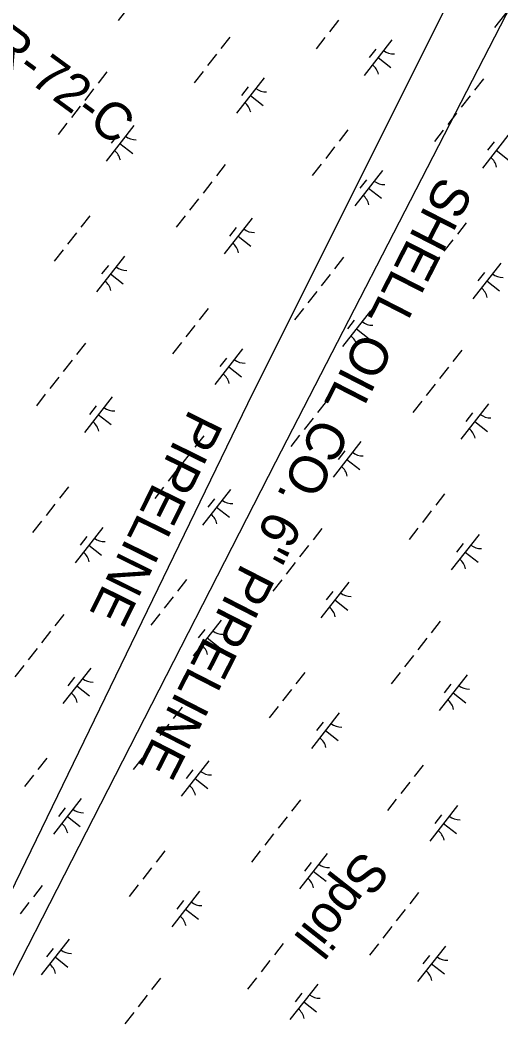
# Model space of a CAD drawing. Extents: x 3896831 to 3918110, y 171006 to 193349.
# Drawn here: x 3907043 to 3907575, y 175242 to 176349 of the extents above; entities that cross this region are included whole.
import ezdxf

# ---------------------------------------------------------------- set-up
doc = ezdxf.new("R2010")
doc.units = 0
for name, color, linetype in [('V-CHAN-SPOL', 7, 'Continuous'), ('V-RIVR-RANG-IDEN', 7, 'Continuous'), ('V-UTIL-IDEN', 7, 'Continuous'), ('V-UTIL-LINE', 7, 'Continuous'), ('V-WETL-SWMP', 7, 'Continuous')]:
    doc.layers.add(name, color=color, linetype=linetype)

msp = doc.modelspace()

# ---------------------------------------------------------------- linework, layer by layer
at = {"layer": 'V-UTIL-LINE'}
for points in [[(3905549.4, 173652.6), (3906763.3, 174938.4), (3906949.5, 175133), (3906970.6, 175166.8), (3907325.9, 175860.5), (3907748.9, 176681), (3908142.2, 177273.2), (3908679.4, 178098), (3908869.7, 178381.4), (3908937.4, 178537.8), (3909170, 179117.3), (3909533.8, 179633.3), (3910092.1, 180424.3), (3910333.2, 180766.9), (3910760.4, 181291.4), (3910921.1, 181524), (3911225.6, 181951.2), (3911822, 182788.6), (3911961.6, 182987.4), (3912147.7, 183114.3), (3912722.9, 183841.8), (3913090.9, 184307.1), (3913848, 185258.8), (3914364, 185910.1)], [(3913133.2, 183520.4), (3913116.3, 183516.1), (3912989.4, 183516.1), (3912744.1, 183393.5), (3911902.4, 182441.8), (3910866.1, 181249.1), (3910603.9, 180953), (3910214.7, 180504.6), (3910138.6, 180390.4), (3909757.9, 179819.4), (3909457.6, 179366.9), (3909009.3, 178685.9), (3908785.1, 178351.7), (3908150.7, 177400.1), (3907770, 176816.4), (3907693.9, 176706.4), (3907647.3, 176630.3), (3907300.5, 175936.6), (3907025.6, 175369.8), (3906945.2, 175204.9), (3906416.5, 174650.8), (3905507.1, 173682.2)]]:
    msp.add_lwpolyline(points, dxfattribs=at)
at = {"layer": 'V-WETL-SWMP'}
for p, q in [((3907182.1, 176388.1), (3907151.2, 176348.7)), ((3907598.7, 176380.4), (3907567.9, 176341)), ((3907395.1, 176349), (3907385.2, 176336.4)), ((3907274.8, 176330.3), (3907264.9, 176317.7)), ((3907380.2, 176330.1), (3907370.4, 176317.5)), ((3907454.4, 176327.4), (3907423.5, 176288)), ((3907436.6, 176317.2), (3907429.2, 176307.8)), ((3907260, 176311.4), (3907250.1, 176298.8)), ((3907439, 176307.7), (3907453.1, 176296.6)), ((3907245.2, 176292.5), (3907235.3, 176279.9)), ((3907138.9, 176291.9), (3907129.1, 176279.3)), ((3907313, 176285.5), (3907282.1, 176246.1)), ((3907555.6, 176284.2), (3907545.7, 176271.6)), ((3907124.1, 176273), (3907114.3, 176260.4)), ((3907295.2, 176275.3), (3907287.8, 176265.8)), ((3907297.6, 176265.8), (3907311.7, 176254.7)), ((3907540.8, 176265.3), (3907530.9, 176252.7)), ((3907109.3, 176254.1), (3907099.5, 176241.5)), ((3907526, 176246.4), (3907516.1, 176233.8)), ((3907094.5, 176235.2), (3907084.7, 176222.6)), ((3907168.7, 176232.5), (3907137.8, 176193.1)), ((3907405.7, 176227.7), (3907395.8, 176215.1)), ((3907511.2, 176227.5), (3907501.3, 176214.9)), ((3907150.9, 176222.3), (3907143.5, 176212.9)), ((3907585.3, 176224.8), (3907554.5, 176185.4)), ((3907567.5, 176214.6), (3907560.1, 176205.2)), ((3907153.2, 176212.8), (3907167.4, 176201.7)), ((3907390.9, 176208.8), (3907381, 176196.2)), ((3907569.9, 176205.1), (3907584, 176194)), ((3907269.9, 176189.3), (3907260, 176176.7)), ((3907376.1, 176189.9), (3907366.2, 176177.3)), ((3907443.9, 176182.8), (3907413.1, 176143.5)), ((3907255.1, 176170.4), (3907245.2, 176157.8)), ((3907426.1, 176172.6), (3907418.7, 176163.2)), ((3907428.5, 176163.2), (3907442.7, 176152.1)), ((3907240.2, 176151.5), (3907230.4, 176138.9)), ((3907120, 176132.7), (3907110.1, 176120.2)), ((3907225.4, 176132.6), (3907215.6, 176120)), ((3907299.6, 176129.9), (3907268.7, 176090.5)), ((3907281.8, 176119.7), (3907274.4, 176110.2)), ((3907536.6, 176125), (3907526.8, 176112.5)), ((3907105.2, 176113.9), (3907095.3, 176101.3)), ((3907284.2, 176110.2), (3907298.3, 176099.1)), ((3907521.8, 176106.2), (3907511.9, 176093.6)), ((3907090.4, 176095), (3907080.5, 176082.4)), ((3907158.2, 176087.9), (3907127.3, 176048.6)), ((3907400.8, 176086.7), (3907390.9, 176074.1)), ((3907507, 176087.3), (3907497.1, 176074.7)), ((3907140.4, 176077.7), (3907133, 176068.3)), ((3907574.8, 176080.2), (3907544, 176040.9)), ((3907142.8, 176068.3), (3907156.9, 176057.2)), ((3907386, 176067.8), (3907376.1, 176055.2)), ((3907557, 176070), (3907549.6, 176060.6)), ((3907559.4, 176060.6), (3907573.6, 176049.5)), ((3907371.2, 176048.9), (3907361.3, 176036.3)), ((3907250.9, 176030.1), (3907241, 176017.5)), ((3907356.4, 176030), (3907346.5, 176017.4)), ((3907430.5, 176027.3), (3907399.7, 175987.9)), ((3907412.7, 176017.1), (3907405.3, 176007.6)), ((3907236.1, 176011.2), (3907226.2, 175998.7)), ((3907415.1, 176007.6), (3907429.2, 175996.5)), ((3907115.1, 175991.8), (3907105.2, 175979.2)), ((3907221.3, 175992.4), (3907211.4, 175979.8)), ((3907289.1, 175985.3), (3907258.3, 175946)), ((3907531.7, 175984.1), (3907521.8, 175971.5)), ((3907100.2, 175972.9), (3907090.4, 175960.3)), ((3907271.3, 175975.1), (3907263.9, 175965.7)), ((3907273.7, 175965.6), (3907287.9, 175954.5)), ((3907516.9, 175965.2), (3907507, 175952.6)), ((3907085.4, 175954), (3907075.6, 175941.4)), ((3907502.1, 175946.3), (3907492.2, 175933.7)), ((3907070.6, 175935.1), (3907060.8, 175922.5)), ((3907144.8, 175932.4), (3907113.9, 175893)), ((3907381.8, 175927.5), (3907371.9, 175914.9)), ((3907487.3, 175927.4), (3907477.4, 175914.8)), ((3907127, 175922.2), (3907119.6, 175912.7)), ((3907561.4, 175924.7), (3907530.6, 175885.3)), ((3907129.3, 175912.7), (3907143.5, 175901.6)), ((3907367, 175908.6), (3907357.1, 175896)), ((3907543.6, 175914.5), (3907536.2, 175905)), ((3907546, 175905), (3907560.2, 175893.9)), ((3907246, 175889.2), (3907236.1, 175876.6)), ((3907352.2, 175889.8), (3907342.3, 175877.2)), ((3907420, 175882.7), (3907389.2, 175843.4)), ((3907402.2, 175872.5), (3907394.8, 175863.1)), ((3907231.2, 175870.3), (3907221.3, 175857.7)), ((3907404.6, 175863), (3907418.8, 175851.9)), ((3907216.4, 175851.4), (3907206.5, 175838.8)), ((3907096.1, 175832.6), (3907086.2, 175820)), ((3907201.6, 175832.5), (3907191.7, 175819.9)), ((3907275.7, 175829.8), (3907244.8, 175790.4)), ((3907257.9, 175819.6), (3907250.5, 175810.1)), ((3907512.7, 175824.9), (3907502.9, 175812.3)), ((3907081.3, 175813.7), (3907071.4, 175801.1)), ((3907260.3, 175810.1), (3907274.4, 175799)), ((3907497.9, 175806), (3907488.1, 175793.4)), ((3907066.5, 175794.8), (3907056.6, 175782.3)), ((3907134.3, 175787.8), (3907103.5, 175748.5)), ((3907376.9, 175786.6), (3907367, 175774)), ((3907483.1, 175787.1), (3907473.3, 175774.6)), ((3907116.5, 175777.6), (3907109.1, 175768.2)), ((3907550.9, 175780.1), (3907520.1, 175740.8)), ((3907118.9, 175768.1), (3907133, 175757)), ((3907362.1, 175767.7), (3907352.2, 175755.1)), ((3907533.1, 175769.9), (3907525.7, 175760.5)), ((3907535.5, 175760.4), (3907549.7, 175749.3)), ((3907347.3, 175748.8), (3907337.4, 175736.2)), ((3907227, 175730), (3907217.1, 175717.4)), ((3907332.5, 175729.9), (3907322.6, 175717.3)), ((3907406.6, 175727.1), (3907375.8, 175687.8)), ((3907388.8, 175717), (3907381.4, 175707.5)), ((3907212.2, 175711.1), (3907202.3, 175698.5)), ((3907391.2, 175707.5), (3907405.4, 175696.4)), ((3907091.2, 175691.6), (3907081.3, 175679)), ((3907197.4, 175692.2), (3907187.5, 175679.6)), ((3907265.2, 175685.2), (3907234.4, 175645.8)), ((3907507.8, 175683.9), (3907497.9, 175671.3)), ((3907076.4, 175672.8), (3907066.5, 175660.2)), ((3907247.4, 175675), (3907240, 175665.6)), ((3907249.8, 175665.5), (3907264, 175654.4)), ((3907493, 175665.1), (3907483.1, 175652.5)), ((3907061.6, 175653.9), (3907051.7, 175641.3)), ((3907478.2, 175646.2), (3907468.3, 175633.6)), ((3907046.7, 175635), (3907036.9, 175622.4)), ((3907120.9, 175632.2), (3907090, 175592.9)), ((3907103.1, 175622), (3907095.7, 175612.6)), ((3907357.9, 175627.4), (3907348.1, 175614.8)), ((3907463.4, 175627.3), (3907453.5, 175614.7)), ((3907537.5, 175624.5), (3907506.7, 175585.2)), ((3907105.5, 175612.6), (3907119.6, 175601.5)), ((3907343.1, 175608.5), (3907333.3, 175595.9)), ((3907519.7, 175614.3), (3907512.3, 175604.9)), ((3907522.1, 175604.9), (3907536.3, 175593.8)), ((3907222.1, 175589), (3907212.2, 175576.4)), ((3907328.3, 175589.6), (3907318.4, 175577)), ((3907396.1, 175582.6), (3907365.3, 175543.2)), ((3907378.3, 175572.4), (3907370.9, 175563)), ((3907207.3, 175570.1), (3907197.4, 175557.6)), ((3907380.7, 175562.9), (3907394.9, 175551.8)), ((3907192.5, 175551.3), (3907182.6, 175538.7)), ((3907072.2, 175532.5), (3907062.3, 175519.9)), ((3907177.7, 175532.4), (3907167.8, 175519.8)), ((3907251.8, 175529.6), (3907221, 175490.3)), ((3907234, 175519.4), (3907226.6, 175510)), ((3907488.8, 175524.8), (3907479, 175512.2)), ((3907057.4, 175513.6), (3907047.5, 175501)), ((3907236.4, 175510), (3907250.5, 175498.9)), ((3907474, 175505.9), (3907464.2, 175493.3)), ((3907110.4, 175487.7), (3907079.6, 175448.3)), ((3907353, 175486.4), (3907343.1, 175473.8)), ((3907459.2, 175487), (3907449.4, 175474.4)), ((3907092.6, 175477.5), (3907085.2, 175468)), ((3907527.1, 175480), (3907496.2, 175440.6)), ((3907095, 175468), (3907109.2, 175456.9)), ((3907338.2, 175467.5), (3907328.3, 175454.9)), ((3907509.3, 175469.8), (3907501.9, 175460.3)), ((3907511.6, 175460.3), (3907525.8, 175449.2)), ((3907323.4, 175448.6), (3907313.5, 175436.1)), ((3907203.1, 175429.9), (3907193.3, 175417.3)), ((3907308.6, 175429.8), (3907298.7, 175417.2)), ((3907382.7, 175427), (3907351.9, 175387.7)), ((3907188.3, 175411), (3907178.4, 175398.4)), ((3907364.9, 175416.8), (3907357.5, 175407.4)), ((3907367.3, 175407.3), (3907381.5, 175396.2)), ((3907067.3, 175391.5), (3907057.4, 175378.9)), ((3907173.5, 175392.1), (3907163.6, 175379.5)), ((3907241.3, 175385.1), (3907210.5, 175345.7)), ((3907483.9, 175383.8), (3907474, 175371.2)), ((3907223.5, 175374.9), (3907216.1, 175365.4)), ((3907052.5, 175372.6), (3907042.6, 175360)), ((3907225.9, 175365.4), (3907240.1, 175354.3)), ((3907469.1, 175364.9), (3907459.2, 175352.3)), ((3907454.3, 175346), (3907444.4, 175333.4)), ((3907097, 175332.1), (3907066.2, 175292.8)), ((3907079.2, 175321.9), (3907071.8, 175312.5)), ((3907334, 175327.3), (3907324.2, 175314.7)), ((3907439.5, 175327.1), (3907429.6, 175314.6)), ((3907513.6, 175324.4), (3907482.8, 175285.1)), ((3907081.6, 175312.4), (3907095.7, 175301.3)), ((3907319.2, 175308.4), (3907309.4, 175295.8)), ((3907495.8, 175314.2), (3907488.4, 175304.8)), ((3907498.2, 175304.7), (3907512.4, 175293.6)), ((3907198.2, 175288.9), (3907188.3, 175276.3)), ((3907304.4, 175289.5), (3907294.6, 175276.9)), ((3907372.2, 175282.5), (3907341.4, 175243.1)), ((3907183.4, 175270), (3907173.5, 175257.4)), ((3907354.5, 175272.3), (3907347.1, 175262.8)), ((3907356.8, 175262.8), (3907371, 175251.7)), ((3907168.6, 175251.1), (3907158.7, 175238.5))]:
    msp.add_line(p, q, dxfattribs=at)
for centre, start, end in [((3907456.2, 176329.3), 231.1403, 272.6839), ((3907422.1, 176285.8), 11.1403, 52.6839), ((3907314.8, 176287.4), 231.1403, 272.6839), ((3907280.7, 176243.9), 11.1403, 52.6839), ((3907170.5, 176234.4), 231.1403, 272.6839), ((3907136.4, 176190.9), 11.1403, 52.6839), ((3907553, 176183.2), 11.1403, 52.6839), ((3907445.7, 176184.8), 231.1403, 272.6839), ((3907411.6, 176141.3), 11.1403, 52.6839), ((3907301.4, 176131.8), 231.1403, 272.6839), ((3907267.3, 176088.3), 11.1403, 52.6839), ((3907160, 176089.8), 231.1403, 272.6839), ((3907125.9, 176046.4), 11.1403, 52.6839), ((3907576.6, 176082.1), 231.1403, 272.6839), ((3907542.6, 176038.7), 11.1403, 52.6839), ((3907432.3, 176029.2), 231.1403, 272.6839), ((3907398.2, 175985.7), 11.1403, 52.6839), ((3907290.9, 175987.2), 231.1403, 272.6839), ((3907256.8, 175943.8), 11.1403, 52.6839), ((3907146.6, 175934.3), 231.1403, 272.6839), ((3907112.5, 175890.8), 11.1403, 52.6839), ((3907563.2, 175926.6), 231.1403, 272.6839), ((3907529.1, 175883.1), 11.1403, 52.6839), ((3907421.8, 175884.6), 231.1403, 272.6839), ((3907387.7, 175841.2), 11.1403, 52.6839), ((3907277.5, 175831.7), 231.1403, 272.6839), ((3907243.4, 175788.2), 11.1403, 52.6839), ((3907136.1, 175789.7), 231.1403, 272.6839), ((3907552.7, 175782), 231.1403, 272.6839), ((3907102, 175746.2), 11.1403, 52.6839), ((3907518.7, 175738.5), 11.1403, 52.6839), ((3907408.4, 175729.1), 231.1403, 272.6839), ((3907374.3, 175685.6), 11.1403, 52.6839), ((3907267, 175687.1), 231.1403, 272.6839), ((3907232.9, 175643.6), 11.1403, 52.6839), ((3907122.7, 175634.2), 231.1403, 272.6839), ((3907539.3, 175626.5), 231.1403, 272.6839), ((3907088.6, 175590.7), 11.1403, 52.6839), ((3907505.3, 175583), 11.1403, 52.6839), ((3907397.9, 175584.5), 231.1403, 272.6839), ((3907363.9, 175541), 11.1403, 52.6839), ((3907253.6, 175531.5), 231.1403, 272.6839), ((3907219.5, 175488.1), 11.1403, 52.6839), ((3907112.2, 175489.6), 231.1403, 272.6839), ((3907528.9, 175481.9), 231.1403, 272.6839), ((3907078.1, 175446.1), 11.1403, 52.6839), ((3907494.8, 175438.4), 11.1403, 52.6839), ((3907384.5, 175428.9), 231.1403, 272.6839), ((3907350.4, 175385.5), 11.1403, 52.6839), ((3907243.1, 175387), 231.1403, 272.6839), ((3907209.1, 175343.5), 11.1403, 52.6839), ((3907098.8, 175334), 231.1403, 272.6839), ((3907515.4, 175326.3), 231.1403, 272.6839), ((3907064.7, 175290.6), 11.1403, 52.6839), ((3907481.4, 175282.9), 11.1403, 52.6839), ((3907374.1, 175284.4), 231.1403, 272.6839), ((3907340, 175240.9), 11.1403, 52.6839)]:
    msp.add_arc(centre, 17.6, start, end, dxfattribs=at)

# ---------------------------------------------------------------- texts
at = {"layer": 'V-CHAN-SPOL'}
msp.add_text('Spoil', height=42, rotation=231.9086, dxfattribs=at).set_placement((3907421.3, 175432.2))
at = {"layer": 'V-RIVR-RANG-IDEN'}
msp.add_text('R-72-C', height=41.5, rotation=323.7689, dxfattribs=at).set_placement((3907004.7, 176315.2))
at = {"layer": 'V-UTIL-IDEN'}
for s, rotation, p in [('SHELL OIL CO. 6" PIPELINE', 242.9062, (3907508, 176178.4)), ('PIPELINE', 243.7515, (3907230.7, 175919.9))]:
    msp.add_text(s, height=42, rotation=rotation, dxfattribs=at).set_placement(p)

doc.saveas('drawing.dxf')
